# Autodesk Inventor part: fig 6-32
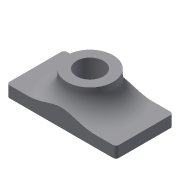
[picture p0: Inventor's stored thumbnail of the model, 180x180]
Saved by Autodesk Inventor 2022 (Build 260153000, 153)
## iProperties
Created: 2004-05
Part Number: fig 6-32
Document SubType Name: Modeling
Designer: CADCIM Technologies
Manufacturer: Standard
Standards Organization: Custom
Density: 1 g/cm^3
Material: Generic
Appearance: Default
Author: CADCIM Technologies
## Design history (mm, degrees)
sketch "Sketch1"
  geometry: L1 (-39.276, -18.692)-(33.721, -18.692); L2 (33.721, -18.692)-(33.721, 19.728); L3 (33.721, 19.728)-(-39.276, 19.728); L4 (-39.276, 19.728)-(-39.276, -18.692)
  constraints: 8 end point, 2 parallel, 1 horizontal, 1 perpendicular
extrude "Extrusion1" new body sketch "Sketch1" distance "d0" = 7.5; taper "d1" = 0 deg
fillet "Fillet1" dims "d2" = 2
sketch "Sketch2"
  geometry: C1 r 15.456 at (-2.778, 0.518)
  constraints: 1 centre point
extrude "Extrusion2" join sketch "Sketch2" distance "d3" = 17.25; taper "d4" = 0 deg
hole "Hole1" diameter "d8" = 18; stored, may be unused: countersink angle "d12" = 90 deg, drill point angle "d14" = 118 deg; dims "d6" = 10, "d7" = 10, "d9" = 6, "d10" = 4, "d11" = 2, "d13" = 8
fillet "Fillet2" dims "d5" = 14
body "Solid1"
